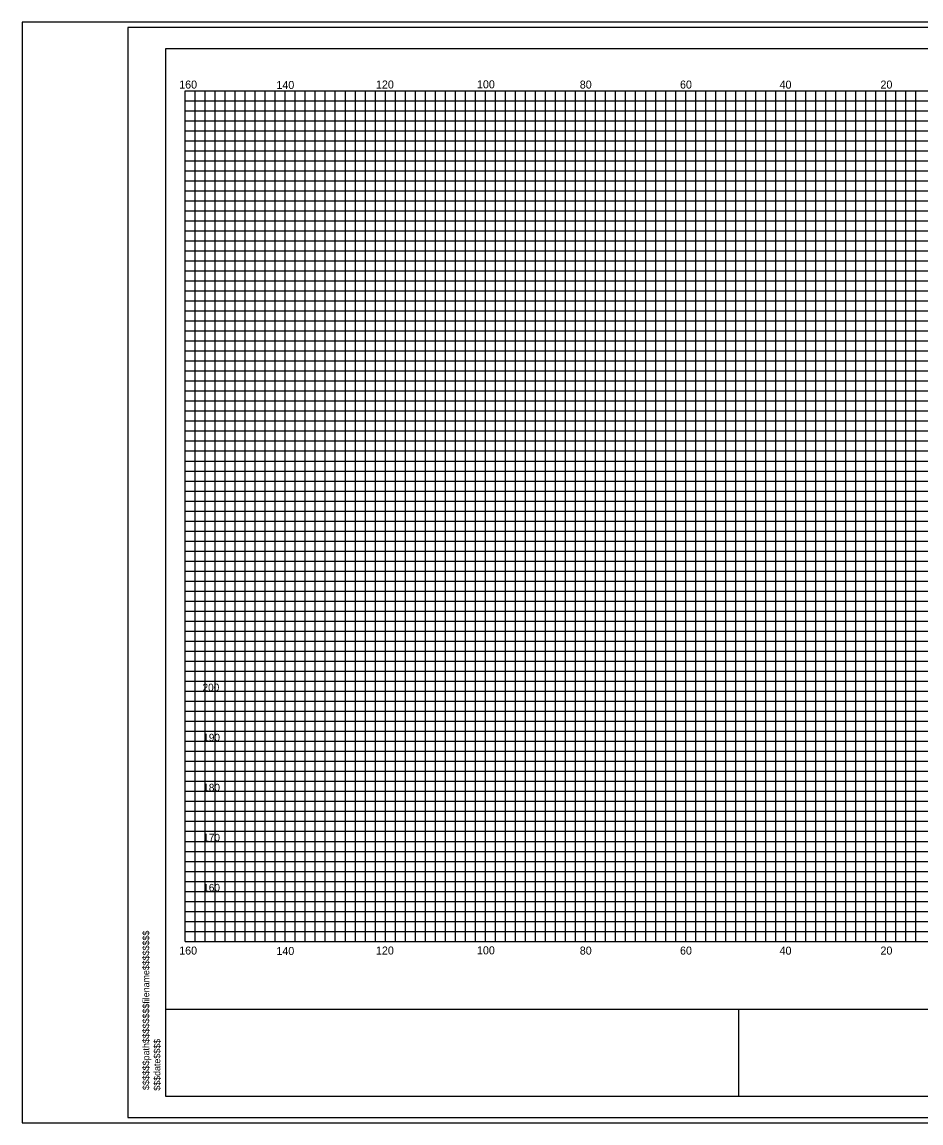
# Model space of a CAD drawing. Extents: x 967 to 1326, y 964 to 3144.
# Drawn here: x 967.4 to 1147, y 2923.7 to 3143.7 of the extents above; entities that cross this region are included whole.
import ezdxf

# ---------------------------------------------------------------- set-up
doc = ezdxf.new("R2010")
doc.units = 0
for name, color, linetype in [('Default', 7, 'Continuous'), ('RD_SHT_Bndy', 7, 'Continuous'), ('RD_SHT_IplotShp', 7, 'Continuous'), ('RD_SHT_MjGrid', 7, 'Continuous'), ('RD_SHT_MnGrid', 7, 'Continuous'), ('RD_SHT_TX', 7, 'Continuous'), ('RD_Sketch1', 7, 'Continuous')]:
    doc.layers.add(name, color=color, linetype=linetype)

msp = doc.modelspace()

# ---------------------------------------------------------------- linework, layer by layer
at = {"layer": 'RD_SHT_Bndy'}
for p, q in [((996.11, 2928.98), (996.11, 3138.46)), ((996.11, 3138.46), (1323.89, 3138.46)), ((996.11, 2946.49), (1323.89, 2946.49)), ((1110.59, 2928.98), (1110.59, 2946.56)), ((1323.89, 2928.98), (996.11, 2928.98))]:
    msp.add_line(p, q, dxfattribs=at)
at = {"layer": 'RD_SHT_IplotShp'}
for points in [[(967.41, 2923.72), (1326.28, 2923.72), (1326.28, 3143.72), (967.41, 3143.72)], [(988.52, 2924.84), (1326.28, 2924.84), (1326.28, 3142.6), (988.52, 3142.6)]]:
    msp.add_lwpolyline(points, close=True, dxfattribs=at)
at = {"layer": 'RD_SHT_MjGrid'}
for p, q in [((1000, 3130), (1320, 3130)), ((1000, 2960), (1000, 3130)), ((1010, 2960), (1010, 3130)), ((1020, 2960), (1020, 3130)), ((1030, 2960), (1030, 3130)), ((1040, 2960), (1040, 3130)), ((1050, 2960), (1050, 3130)), ((1060, 2960), (1060, 3130)), ((1070, 2960), (1070, 3130)), ((1080, 2960), (1080, 3130)), ((1090, 2960), (1090, 3130)), ((1100, 2960), (1100, 3130)), ((1110, 2960), (1110, 3130)), ((1120, 2960), (1120, 3130)), ((1130, 2960), (1130, 3130)), ((1140, 2960), (1140, 3130)), ((1000, 3120), (1320, 3120)), ((1000, 3110), (1320, 3110)), ((1000, 3100), (1320, 3100)), ((1000, 3090), (1320, 3090)), ((1000, 3080), (1320, 3080)), ((1000, 3070), (1320, 3070)), ((1000, 3060), (1320, 3060)), ((1000, 3050), (1320, 3050)), ((1000, 3040), (1320, 3040)), ((1000, 3030), (1320, 3030)), ((1000, 3020), (1320, 3020)), ((1000, 3010), (1320, 3010)), ((1000, 3000), (1320, 3000)), ((1000, 2990), (1320, 2990)), ((1000, 2980), (1320, 2980)), ((1000, 2970), (1320, 2970)), ((1000, 2960), (1320, 2960))]:
    msp.add_line(p, q, dxfattribs=at)
at = {"layer": 'RD_SHT_MnGrid'}
for p, q in [((1002, 2960), (1002, 3130)), ((1004, 2960), (1004, 3130)), ((1006, 2960), (1006, 3130)), ((1008, 2960), (1008, 3130)), ((1012, 2960), (1012, 3130)), ((1014, 2960), (1014, 3130)), ((1016, 2960), (1016, 3130)), ((1018, 2960), (1018, 3130)), ((1022, 2960), (1022, 3130)), ((1024, 2960), (1024, 3130)), ((1026, 2960), (1026, 3130)), ((1028, 2960), (1028, 3130)), ((1032, 2960), (1032, 3130)), ((1034, 2960), (1034, 3130)), ((1036, 2960), (1036, 3130)), ((1038, 2960), (1038, 3130)), ((1042, 2960), (1042, 3130)), ((1044, 2960), (1044, 3130)), ((1046, 2960), (1046, 3130)), ((1048, 2960), (1048, 3130)), ((1052, 2960), (1052, 3130)), ((1054, 2960), (1054, 3130)), ((1056, 2960), (1056, 3130)), ((1058, 2960), (1058, 3130)), ((1062, 2960), (1062, 3130)), ((1064, 2960), (1064, 3130)), ((1066, 2960), (1066, 3130)), ((1068, 2960), (1068, 3130)), ((1072, 2960), (1072, 3130)), ((1074, 2960), (1074, 3130)), ((1076, 2960), (1076, 3130)), ((1078, 2960), (1078, 3130)), ((1082, 2960), (1082, 3130)), ((1084, 2960), (1084, 3130)), ((1086, 2960), (1086, 3130)), ((1088, 2960), (1088, 3130)), ((1092, 2960), (1092, 3130)), ((1094, 2960), (1094, 3130)), ((1096, 2960), (1096, 3130)), ((1098, 2960), (1098, 3130)), ((1102, 2960), (1102, 3130)), ((1104, 2960), (1104, 3130)), ((1106, 2960), (1106, 3130)), ((1108, 2960), (1108, 3130)), ((1112, 2960), (1112, 3130)), ((1114, 2960), (1114, 3130)), ((1116, 2960), (1116, 3130)), ((1118, 2960), (1118, 3130)), ((1122, 2960), (1122, 3130)), ((1124, 2960), (1124, 3130)), ((1126, 2960), (1126, 3130)), ((1128, 2960), (1128, 3130)), ((1132, 2960), (1132, 3130)), ((1134, 2960), (1134, 3130)), ((1136, 2960), (1136, 3130)), ((1138, 2960), (1138, 3130)), ((1142, 2960), (1142, 3130)), ((1144, 2960), (1144, 3130)), ((1146, 2960), (1146, 3130)), ((1000, 3128), (1320, 3128)), ((1000, 3126), (1320, 3126)), ((1000, 3124), (1320, 3124)), ((1000, 3122), (1320, 3122)), ((1000, 3118), (1320, 3118)), ((1000, 3116), (1320, 3116)), ((1000, 3114), (1320, 3114)), ((1000, 3112), (1320, 3112)), ((1000, 3108), (1320, 3108)), ((1000, 3106), (1320, 3106)), ((1000, 3104), (1320, 3104)), ((1000, 3102), (1320, 3102)), ((1000, 3098), (1320, 3098)), ((1000, 3096), (1320, 3096)), ((1000, 3094), (1320, 3094)), ((1000, 3092), (1320, 3092)), ((1000, 3088), (1320, 3088)), ((1000, 3086), (1320, 3086)), ((1000, 3084), (1320, 3084)), ((1000, 3082), (1320, 3082)), ((1000, 3078), (1320, 3078)), ((1000, 3076), (1320, 3076)), ((1000, 3074), (1320, 3074)), ((1000, 3072), (1320, 3072)), ((1000, 3068), (1320, 3068)), ((1000, 3066), (1320, 3066)), ((1000, 3064), (1320, 3064)), ((1000, 3062), (1320, 3062)), ((1000, 3058), (1320, 3058)), ((1000, 3056), (1320, 3056)), ((1000, 3054), (1320, 3054)), ((1000, 3052), (1320, 3052)), ((1000, 3048), (1320, 3048)), ((1000, 3046), (1320, 3046)), ((1000, 3044), (1320, 3044)), ((1000, 3042), (1320, 3042)), ((1000, 3038), (1320, 3038)), ((1000, 3036), (1320, 3036)), ((1000, 3034), (1320, 3034)), ((1000, 3032), (1320, 3032)), ((1000, 3028), (1320, 3028)), ((1000, 3026), (1320, 3026)), ((1000, 3024), (1320, 3024)), ((1000, 3022), (1320, 3022)), ((1000, 3018), (1320, 3018)), ((1000, 3016), (1320, 3016)), ((1000, 3014), (1320, 3014)), ((1000, 3012), (1320, 3012)), ((1000, 3008), (1320, 3008)), ((1000, 3006), (1320, 3006)), ((1000, 3004), (1320, 3004)), ((1000, 3002), (1320, 3002)), ((1000, 2998), (1320, 2998)), ((1000, 2996), (1320, 2996)), ((1000, 2994), (1320, 2994)), ((1000, 2992), (1320, 2992)), ((1000, 2988), (1320, 2988)), ((1000, 2986), (1320, 2986)), ((1000, 2984), (1320, 2984)), ((1000, 2982), (1320, 2982)), ((1000, 2978), (1320, 2978)), ((1000, 2976), (1320, 2976)), ((1000, 2974), (1320, 2974)), ((1000, 2972), (1320, 2972)), ((1000, 2968), (1320, 2968)), ((1000, 2966), (1320, 2966)), ((1000, 2964), (1320, 2964)), ((1000, 2962), (1320, 2962))]:
    msp.add_line(p, q, dxfattribs=at)
at = {"layer": 'RD_Sketch1'}
msp.add_lwpolyline([(967.41, 2923.72), (1326.28, 2923.72), (1326.28, 3143.72), (967.41, 3143.72)], close=True, dxfattribs=at)

# ---------------------------------------------------------------- texts
at = {"layer": 'Default'}
for s, p in [('200', (1003.47, 3010)), ('190', (1003.61, 3000)), ('180', (1003.61, 2990)), ('170', (1003.61, 2980)), ('160', (1003.61, 2970))]:
    msp.add_text(s, height=1.5, dxfattribs=at).set_placement(p)
for s, p in [('$$$$$$path$$$$$$$$filename$$$$$$$$', (992.83, 2930.31)), ('$$$date$$$$', (995.04, 2930.17))]:
    msp.add_text(s, height=1.3258, rotation=90, dxfattribs=at).set_placement(p)
at = {"layer": 'RD_SHT_TX'}
for s, p in [('160', (998.81, 3130.42)), ('140', (1018.23, 3130.34)), ('120', (1038.12, 3130.43)), ('100', (1058.3, 3130.47)), ('80', (1078.84, 3130.42)), ('60', (1098.86, 3130.42)), ('40', (1118.75, 3130.41)), ('20', (1138.91, 3130.42)), ('120', (1038.12, 2957.38)), ('100', (1058.3, 2957.42)), ('160', (998.81, 2957.37)), ('140', (1018.23, 2957.29)), ('80', (1078.84, 2957.37)), ('60', (1098.86, 2957.37)), ('40', (1118.75, 2957.36)), ('20', (1138.91, 2957.37))]:
    msp.add_text(s, height=1.6, dxfattribs=at).set_placement(p)

doc.saveas('drawing.dxf')
